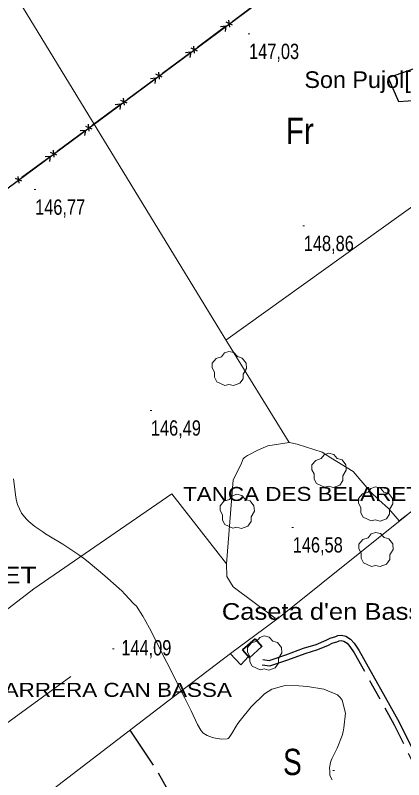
# Model space of a CAD drawing. Extents: x -807245 to 6129983, y -54972206 to 262146364.
# Drawn here: x 489465.5 to 489687.7, y 4383529.7 to 4383966.6 of the extents above; entities that cross this region are included whole.
import ezdxf
from ezdxf.enums import TextEntityAlignment as Align

# ---------------------------------------------------------------- set-up
doc = ezdxf.new("R2010")
doc.units = 0
doc.header["$LTSCALE"] = 4
doc.linetypes.add('LONG_DASHED', pattern=[7.5, 6, -1.5])
doc.linetypes.add('MEDIUM_DASHED', pattern=[4.5, 3, -1.5])
for name, color, linetype, lineweight in [('25', 7, 'LONG_DASHED', 25), ('27', 7, 'Continuous', 25), ('29', 7, 'Continuous', 13), ('38', 7, 'Continuous', 25), ('43', 7, 'Continuous', 25), ('47', 7, 'Continuous', 35), ('51', 7, 'Continuous', 13), ('7', 7, 'Continuous', 13), ('9', 7, 'Continuous', 13)]:
    doc.layers.add(name, color=color, linetype=linetype, lineweight=lineweight)
doc.layers.add('31', color=7, linetype='Continuous')
doc.layers.add('5', color=7, linetype='Continuous')

msp = doc.modelspace()

# ---------------------------------------------------------------- linework, layer by layer
at = {"layer": '25'}
for points in [[(489697.95, 4383937.57), (489678.81, 4383930.77), (489684.74, 4383917.35), (489695.7, 4383918.05), (489698.04, 4383919.3), (489732.24, 4383878.92), (489777.89, 4383917.46)], [(489531.01, 4383557.93), (489547.21, 4383533.67), (489566.99, 4383498.64), (489586.73, 4383459.63), (489597.25, 4383441.35), (489614.79, 4383404.77)]]:
    msp.add_lwpolyline(points, dxfattribs=at)
at = {"layer": '27'}
msp.add_spline([(491255.21, 4383970.03), (491244.34, 4383967.52), (491230.36, 4383957.66), (491230.81, 4383957.81), (491230.81, 4383957.81), (491220.15, 4383951.47), (491212.7, 4383943.01), (491205.06, 4383944.23), (491184.85, 4383957.71), (491152.82, 4383981.27), (491128.36, 4384004.58), (491128.29, 4384004.88), (491122.26, 4384021.39), (491095.75, 4384034.59), (491071.07, 4384059.32), (491064.71, 4384065.12)], degree=3, dxfattribs=at)
at = {"layer": '29'}
for points in [[(489585.34, 4383755.01), (489580.8, 4383757.13), (489579.39, 4383759.67), (489579.49, 4383762.65), (489578.12, 4383765.06), (489578.16, 4383767.81), (489580.32, 4383770.41), (489583.51, 4383771.41), (489585.16, 4383773.6), (489587.73, 4383774.43), (489590.59, 4383773.78), (489592.54, 4383771.51), (489595.35, 4383770.69), (489597.48, 4383767.84), (489597.72, 4383764.71), (489595.84, 4383761.56), (489595.84, 4383758.88), (489594.02, 4383756.27), (489590.4, 4383754.93), (489587.63, 4383755.56)], [(489642.37, 4383696.82), (489637.83, 4383698.94), (489636.42, 4383701.48), (489636.52, 4383704.46), (489635.15, 4383706.87), (489635.19, 4383709.62), (489637.35, 4383712.22), (489640.54, 4383713.22), (489642.19, 4383715.41), (489644.76, 4383716.24), (489647.62, 4383715.59), (489649.57, 4383713.32), (489652.38, 4383712.5), (489654.51, 4383709.65), (489654.75, 4383706.52), (489652.87, 4383703.37), (489652.87, 4383700.69), (489651.05, 4383698.08), (489647.43, 4383696.74), (489644.66, 4383697.37)], [(489669.09, 4383677.61), (489664.55, 4383679.73), (489663.14, 4383682.27), (489663.24, 4383685.25), (489661.87, 4383687.66), (489661.91, 4383690.41), (489664.07, 4383693.01), (489667.26, 4383694.01), (489668.91, 4383696.2), (489671.48, 4383697.03), (489674.34, 4383696.38), (489676.29, 4383694.11), (489679.1, 4383693.29), (489681.23, 4383690.44), (489681.47, 4383687.31), (489679.59, 4383684.16), (489679.59, 4383681.48), (489677.77, 4383678.87), (489674.15, 4383677.53), (489671.38, 4383678.16)], [(489589.89, 4383673.41), (489585.35, 4383675.53), (489583.94, 4383678.07), (489584.04, 4383681.05), (489582.67, 4383683.46), (489582.71, 4383686.21), (489584.87, 4383688.81), (489588.06, 4383689.81), (489589.71, 4383692), (489592.28, 4383692.83), (489595.14, 4383692.18), (489597.09, 4383689.91), (489599.9, 4383689.09), (489602.03, 4383686.24), (489602.27, 4383683.11), (489600.39, 4383679.96), (489600.39, 4383677.28), (489598.57, 4383674.67), (489594.95, 4383673.33), (489592.18, 4383673.96)], [(489669.24, 4383651.58), (489664.7, 4383653.7), (489663.29, 4383656.24), (489663.39, 4383659.22), (489662.02, 4383661.63), (489662.06, 4383664.38), (489664.22, 4383666.98), (489667.41, 4383667.98), (489669.06, 4383670.17), (489671.63, 4383671), (489674.49, 4383670.35), (489676.44, 4383668.08), (489679.25, 4383667.26), (489681.38, 4383664.41), (489681.62, 4383661.28), (489679.74, 4383658.13), (489679.74, 4383655.45), (489677.92, 4383652.84), (489674.3, 4383651.5), (489671.53, 4383652.13)], [(489605.55, 4383592.44), (489601.01, 4383594.56), (489599.6, 4383597.1), (489599.7, 4383600.08), (489598.33, 4383602.49), (489598.37, 4383605.24), (489600.53, 4383607.84), (489603.72, 4383608.84), (489605.37, 4383611.03), (489607.94, 4383611.86), (489610.8, 4383611.21), (489612.75, 4383608.94), (489615.56, 4383608.12), (489617.69, 4383605.27), (489617.93, 4383602.14), (489616.05, 4383598.99), (489616.05, 4383596.31), (489614.23, 4383593.7), (489610.61, 4383592.36), (489607.84, 4383592.99)]]:
    msp.add_lwpolyline(points, close=True, dxfattribs=at)
at = {"layer": '38'}
msp.add_lwpolyline([(489607.15, 4383598.44), (489610.72, 4383597.86), (489620.29, 4383601.14), (489630.34, 4383604.79), (489637.52, 4383607.02), (489643.26, 4383609.45), (489645.53, 4383610.66), (489648.82, 4383611.62), (489649.95, 4383612.12), (489652.01, 4383612.29), (489654.54, 4383611.79), (489657.26, 4383610), (489659.32, 4383607.8), (489662, 4383603.79), (489684.99, 4383562.48), (489706.56, 4383519.07), (489722.66, 4383488.23)], dxfattribs=at)
at = {"layer": '38', "linetype": 'MEDIUM_DASHED'}
msp.add_lwpolyline([(489606.65, 4383595.38), (489611, 4383594.68), (489621.33, 4383598.22), (489631.32, 4383601.85), (489638.58, 4383604.1), (489644.6, 4383606.65), (489646.71, 4383607.78), (489649.9, 4383608.7), (489650.73, 4383609.08), (489651.83, 4383609.17), (489653.34, 4383608.87), (489655.24, 4383607.62), (489656.88, 4383605.86), (489659.36, 4383602.17), (489682.25, 4383561.04), (489703.8, 4383517.67), (489720.17, 4383486.31)], dxfattribs=at)
at = {"layer": '43'}
for p, q in [((489589.84, 4383963.29), (489605.91, 4383975.19)), ((489589.76, 4383961.05), (489586.1, 4383962.64)), ((489588.16, 4383959.86), (489587.7, 4383963.83)), ((489569.75, 4383948.41), (489585.82, 4383960.31)), ((489585.92, 4383960.36), (489582.93, 4383960.02)), ((489585.92, 4383960.36), (489585.47, 4383957.4)), ((489568.07, 4383944.98), (489567.61, 4383948.95)), ((489549.66, 4383933.53), (489565.73, 4383945.43)), ((489565.82, 4383945.48), (489562.84, 4383945.14)), ((489565.82, 4383945.48), (489565.38, 4383942.52)), ((489569.67, 4383946.17), (489566.01, 4383947.76)), ((489529.57, 4383918.65), (489545.64, 4383930.55)), ((489545.73, 4383930.6), (489542.75, 4383930.26)), ((489545.73, 4383930.6), (489545.29, 4383927.64)), ((489549.58, 4383931.29), (489545.92, 4383932.88)), ((489547.98, 4383930.1), (489547.52, 4383934.07)), ((489529.49, 4383916.41), (489525.83, 4383918)), ((489527.88, 4383915.22), (489527.43, 4383919.19)), ((489509.48, 4383903.77), (489525.55, 4383915.67)), ((489525.64, 4383915.72), (489522.66, 4383915.38)), ((489525.64, 4383915.72), (489525.2, 4383912.76)), ((489507.79, 4383900.34), (489507.34, 4383904.31)), ((489489.39, 4383888.89), (489505.46, 4383900.79)), ((489505.55, 4383900.85), (489502.57, 4383900.5)), ((489505.55, 4383900.85), (489505.11, 4383897.88)), ((489509.4, 4383901.53), (489505.74, 4383903.12)), ((489489.31, 4383886.65), (489485.64, 4383888.24)), ((489487.7, 4383885.46), (489487.25, 4383889.43)), ((489469.3, 4383874.01), (489485.37, 4383885.91)), ((489485.46, 4383885.97), (489482.48, 4383885.63)), ((489485.46, 4383885.97), (489485.02, 4383883)), ((489467.61, 4383870.58), (489467.16, 4383874.55)), ((489469.22, 4383871.77), (489465.55, 4383873.36))]:
    msp.add_line(p, q, dxfattribs=at)
msp.add_lwpolyline([(488001.89, 4382789.17), (488218.68, 4382951.32), (488457.31, 4383127.02), (488717.97, 4383320.4), (489027.99, 4383545.91), (489266.87, 4383724.08), (489744.68, 4384077.94)], dxfattribs=at)
at = {"layer": '47'}
msp.add_lwpolyline([(489602.62, 4383610.24), (489595.46, 4383603.82), (489599.42, 4383599.4), (489606.58, 4383605.82)], close=True, dxfattribs=at)
at = {"layer": '51'}
for p, q in [((489585.97, 4383780.87), (489706.83, 4383867.66)), ((489436.22, 4383544.32), (489497.27, 4383588.63))]:
    msp.add_line(p, q, dxfattribs=at)
for points in [[(489469.65, 4383971.43), (489584.93, 4383782.54), (489622.13, 4383722.33), (489626.69, 4383721.45), (489641.04, 4383716.86), (489646.03, 4383713.65), (489658.7, 4383705.78), (489664.25, 4383699.34), (489668.62, 4383694.19), (489673.45, 4383689.71), (489678.94, 4383684.77), (489682.87, 4383680.22), (489685.01, 4383677.57), (489802.31, 4383767.09), (489888.67, 4383833.48)], [(489586.3, 4383653.04), (489590.15, 4383701.09), (489594.52, 4383709.66), (489595.84, 4383713.1), (489596.6, 4383713.84), (489598.34, 4383714.95), (489604.68, 4383718.32), (489609.95, 4383720.44), (489622.13, 4383722.33)], [(489377.27, 4383340.19), (489357.96, 4383364.7), (489340.93, 4383385), (489334.36, 4383393.78), (489321.88, 4383405.18), (489302.06, 4383423.63), (489252.74, 4383473.56), (489367.1, 4383555.15), (489476.08, 4383638.76), (489555.1, 4383693.01), (489586.3, 4383653.04), (489586.45, 4383645.91), (489590.13, 4383639.94), (489614.23, 4383622.04)], [(489334.68, 4383393.37), (489385.09, 4383441.67), (489413.58, 4383466.78), (489426.14, 4383476.01), (489489.73, 4383526.38), (489552.78, 4383574.57), (489589.33, 4383602.37), (489616.49, 4383622.46), (489689.4, 4383680.83)], [(489588.47, 4383601.72), (489594.57, 4383595.4), (489598.88, 4383600.01)]]:
    msp.add_lwpolyline(points, dxfattribs=at)
at = {"layer": '7'}
for p, q in [((489598.7, 4383955.98), (489599.7, 4383955.98)), ((489476.3, 4383866.97), (489477.3, 4383866.97)), ((489630.01, 4383846.24), (489631.01, 4383846.24)), ((489542.54, 4383740.71), (489543.54, 4383740.71)), ((489623.7, 4383673.91), (489624.7, 4383673.91)), ((489521.11, 4383604.56), (489522.11, 4383604.56)), ((489647.1, 4383534.93), (489648.1, 4383534.93))]:
    msp.add_line(p, q, dxfattribs=at)
at = {"layer": '9'}
msp.add_lwpolyline([(489646.75, 4383529.54), (489645.44, 4383532.07), (489645.46, 4383533.6), (489645.44, 4383534.07), (489645.41, 4383534.56), (489645.25, 4383536.51), (489645.78, 4383539.5), (489646.19, 4383540.65), (489646.71, 4383541.95), (489649.57, 4383547.79), (489652.49, 4383554.95), (489653.06, 4383557.08), (489653.52, 4383559.27), (489654.3, 4383567.68), (489652.46, 4383575.16), (489651.27, 4383576.75), (489649.78, 4383578.14), (489641.92, 4383581.46), (489632.56, 4383582.96), (489630.13, 4383583.21), (489627.76, 4383583.39), (489619.8, 4383583.43), (489612.26, 4383581.33), (489610.16, 4383580.15), (489608.07, 4383578.71), (489600.47, 4383571.36), (489594.14, 4383563.51), (489592.84, 4383561.76), (489591.75, 4383560.18), (489589.43, 4383556.01), (489587.88, 4383553.71), (489587.27, 4383553.31), (489586.59, 4383553.01), (489583.45, 4383552.82), (489579.98, 4383553.43), (489579.08, 4383553.64), (489578.2, 4383553.87), (489575.28, 4383554.88), (489572.76, 4383556.54), (489572.15, 4383557.19), (489571.57, 4383557.92), (489569.79, 4383561.23), (489566.16, 4383569), (489564.42, 4383572.55), (489562.36, 4383576.7), (489552.26, 4383596.72), (489542.18, 4383616.21), (489540.13, 4383620.03), (489538.4, 4383623.17), (489534.82, 4383628.8), (489533.35, 4383630.11), (489532.94, 4383630.53), (489532.54, 4383630.97), (489531.08, 4383632.75), (489528, 4383635.99), (489526.57, 4383637.35), (489524.89, 4383638.92), (489516.75, 4383646.24), (489507.11, 4383654.26), (489504.49, 4383656.25), (489501.88, 4383658.16), (489492.65, 4383664.22), (489484.64, 4383669.11), (489482.82, 4383670.26), (489481.16, 4383671.32), (489476.58, 4383674.45), (489473.29, 4383677.17), (489472.45, 4383677.97), (489471.64, 4383678.79), (489468.96, 4383681.95), (489466.75, 4383686.98), (489466.24, 4383688.98), (489465.77, 4383691.25), (489464.45, 4383701.64)], dxfattribs=at)

# ---------------------------------------------------------------- texts
at = {"layer": '31'}
for s, width, p in [('Fr', 0.85, (489628.26, 4383893.05)), ('S', 0.8, (489624.02, 4383532.33))]:
    msp.add_text(s, height=15, dxfattribs=dict(at, width=width)).set_placement(p, align=Align.CENTER)
at = {"layer": '5'}
for s, height, width, p in [('Son Pujol[', 9.5, 1.05, (489691.68, 4383925.07)), ('TANCA DES BELARET', 8, 1.2, (489696.97, 4383689)), ('TANCA DES PINARET', 9.5, 1.2, (489477.76, 4383641.85)), ("Caseta d'en Bassa", 9.5, 1.15, (489705.81, 4383621.1)), ('TANCA DE DARRERA CAN BASSA', 8, 1.2, (489589.37, 4383577.03))]:
    msp.add_text(s, height=height, dxfattribs=dict(at, width=width)).set_placement(p, align=Align.RIGHT)
at = {"layer": '7', "width": 0.8}
for s, p in [('147,03', (489599.2, 4383941.61)), ('146,77', (489476.8, 4383852.6)), ('148,86', (489630.51, 4383831.87)), ('146,49', (489543.04, 4383726.34)), ('146,58', (489624.2, 4383659.54)), ('144,09', (489526.12, 4383600.71))]:
    msp.add_text(s, height=8.75, dxfattribs=at).set_placement(p)

doc.saveas('drawing.dxf')
